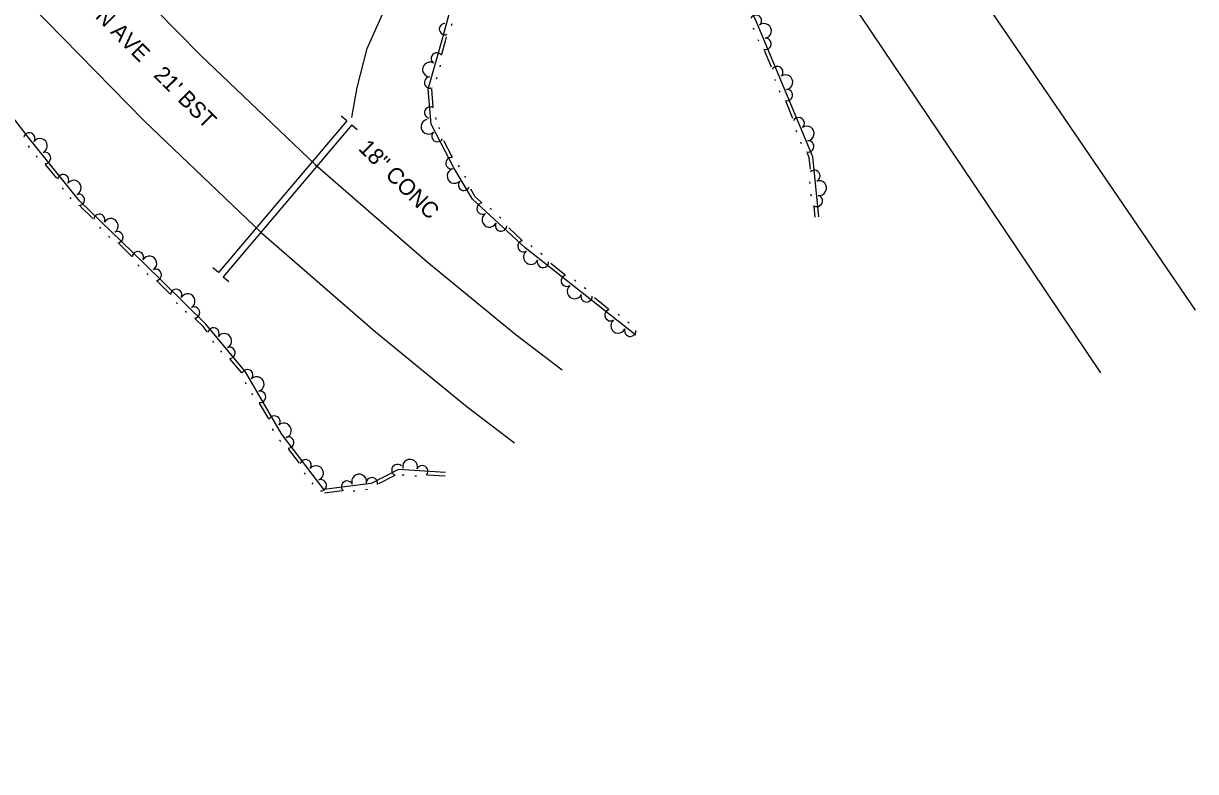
# Model space of a CAD drawing. Extents: x 2030130 to 2036320, y 723205 to 762423.
# Drawn here: x 2034404.8 to 2034673.1, y 759268.4 to 759439.7 of the extents above; entities that cross this region are included whole.
import ezdxf

# ---------------------------------------------------------------- set-up
doc = ezdxf.new("R2010")
doc.units = 0
for name, color, linetype in [('Draft_Station Labels Major', 7, 'Continuous'), ('Draft_Station Tics Major', 7, 'Continuous'), ('Draft_Station Tics Minor', 7, 'Continuous'), ('Old_Level_23', 7, 'Continuous'), ('Old_Level_26', 7, 'Continuous'), ('Prop Alignment Horizontal', 7, 'Continuous')]:
    doc.layers.add(name, color=color, linetype=linetype)

msp = doc.modelspace()

# ---------------------------------------------------------------- linework, layer by layer
at = {"layer": 'Draft_Station Labels Major'}
for points in [[(2034673.1, 759374.03), (2034641.13, 759420.91), (2034612.37, 759462.99), (2034584.85, 759503.64), (2034556.5, 759545.4), (2034528.56, 759586.42), (2034500.61, 759627.72), (2034473.04, 759669.67), (2034444.47, 759710.51), (2034416.72, 759751.28), (2034388.73, 759792.32), (2034360.74, 759833.62)], [(2034339.29, 759819.51), (2034367.32, 759778.28), (2034395.22, 759737.17), (2034423.09, 759695.79), (2034451.3, 759654.89), (2034478.88, 759613.26), (2034507.24, 759572.41), (2034535.18, 759531.29), (2034563.29, 759490.2), (2034591.25, 759449.01), (2034619.59, 759406.87), (2034651.36, 759359.7)], [(2034193.98, 759703.56), (2034287.73, 759602.79), (2034370.61, 759511.86), (2034419.72, 759458.43), (2034445.33, 759432.37), (2034471.55, 759407.33), (2034497.11, 759385.14), (2034517.55, 759368.37), (2034528.08, 759360.37)], [(2034181.13, 759691.91), (2034274.16, 759588.48), (2034357, 759497.6), (2034406.36, 759443.89), (2034432.44, 759417.35), (2034459.25, 759391.75), (2034485.39, 759369.06), (2034506.34, 759351.88), (2034517.18, 759343.65)]]:
    msp.add_lwpolyline(points, dxfattribs=at)
at = {"layer": 'Draft_Station Tics Major'}
for points in [[(2034544.97, 759368.28), (2034519.62, 759388.26), (2034507.55, 759399.45), (2034503.31, 759406.6), (2034498.11, 759416.6), (2034497.43, 759424.62), (2034500.6, 759435.9), (2034503.15, 759445.18), (2034505.1, 759457.43), (2034504.57, 759469.06), (2034502.54, 759482.83), (2034501.29, 759493.73), (2034505.68, 759503.68), (2034511.5, 759511.58), (2034516.43, 759515.13), (2034527.13, 759508.33), (2034541.93, 759494.81), (2034557.48, 759466.95), (2034572.3, 759440.67), (2034585.41, 759409.2), (2034586.75, 759395.36)], [(2034501.4, 759336.81), (2034490.6, 759337.52), (2034484.36, 759334.29), (2034473.58, 759332.95), (2034463.89, 759345.71), (2034455.6, 759359.89), (2034446.5, 759370.82), (2034432.26, 759384.88), (2034417.64, 759399.08), (2034405.88, 759413.63), (2034393.67, 759429.47), (2034382.54, 759442.06), (2034369.68, 759457.9), (2034353.76, 759468), (2034338.78, 759465.82), (2034335.89, 759451.72), (2034333.06, 759435.72), (2034328.81, 759415.39), (2034335.67, 759393.1), (2034347.17, 759361.24), (2034361.18, 759331.95), (2034373.76, 759305.96), (2034386.26, 759281.41), (2034393.72, 759268.38)], [(2034502.79, 759439.22), (2034502.9, 759439.62)], [(2034571.8, 759438.67), (2034571.95, 759438.29)], [(2034500.53, 759432.61), (2034501.39, 759435.68), (2034501.63, 759436.57)], [(2034572.9, 759436.02), (2034573.06, 759435.64)], [(2034574.38, 759433.53), (2034575.96, 759429.74)], [(2034500.15, 759429.74), (2034500.26, 759430.13)], [(2034499.37, 759426.97), (2034499.48, 759427.37)], [(2034576.68, 759426.93), (2034576.84, 759426.56)], [(2034498.6, 759420.52), (2034498.26, 759424.61)], [(2034577.79, 759424.28), (2034577.95, 759423.91)], [(2034579.27, 759421.79), (2034580.85, 759418.01)], [(2034499.26, 759417.7), (2034499.22, 759418.11)], [(2034500.07, 759415.5), (2034499.88, 759415.87)], [(2034581.57, 759415.2), (2034581.73, 759414.82)], [(2034406.19, 759411.28), (2034405.93, 759411.6)], [(2034502.92, 759409.13), (2034501.03, 759412.77)], [(2034582.68, 759412.55), (2034582.83, 759412.17)], [(2034408, 759409.05), (2034407.74, 759409.37)], [(2034584.16, 759410.05), (2034584.6, 759408.99), (2034584.86, 759406.3)], [(2034412.44, 759404.21), (2034409.86, 759407.39)], [(2034504.6, 759406.84), (2034504.39, 759407.2)], [(2034506.06, 759404.37), (2034505.85, 759404.73)], [(2034584.73, 759403.4), (2034584.77, 759402.99)], [(2034413.93, 759401.72), (2034413.67, 759402.04)], [(2034415.74, 759399.48), (2034415.48, 759399.8)], [(2034509.56, 759398.71), (2034508.19, 759399.97), (2034507.17, 759401.69)], [(2034585.01, 759400.55), (2034585.05, 759400.14)], [(2034420.69, 759394.98), (2034417.75, 759397.83)], [(2034511.94, 759397.06), (2034511.64, 759397.33)], [(2034585.69, 759397.73), (2034585.93, 759395.28)], [(2034514.05, 759395.1), (2034513.75, 759395.38)], [(2034422.47, 759392.68), (2034422.17, 759392.97)], [(2034518.88, 759390.06), (2034515.87, 759392.85)], [(2034424.52, 759390.68), (2034424.23, 759390.97)], [(2034429.52, 759386.4), (2034426.58, 759389.26)], [(2034521.25, 759388.54), (2034520.93, 759388.8)], [(2034523.5, 759386.77), (2034523.18, 759387.02)], [(2034431.29, 759384.11), (2034431, 759384.4)], [(2034528.73, 759382.13), (2034525.5, 759384.67)], [(2034433.33, 759382.1), (2034433.04, 759382.39)], [(2034531.23, 759380.67), (2034530.91, 759380.93)], [(2034438.28, 759377.78), (2034435.37, 759380.66)], [(2034533.49, 759378.9), (2034533.17, 759379.15)], [(2034440.04, 759375.47), (2034439.75, 759375.76)], [(2034538.71, 759374.26), (2034535.49, 759376.8)], [(2034442.08, 759373.46), (2034441.79, 759373.74)], [(2034541.22, 759372.81), (2034540.9, 759373.06)], [(2034446.87, 759369.09), (2034445.89, 759370.27), (2034444.12, 759372.02)], [(2034543.47, 759371.03), (2034543.15, 759371.28)], [(2034448.39, 759366.62), (2034448.13, 759366.94)], [(2034450.23, 759364.42), (2034449.97, 759364.73)], [(2034454.74, 759359.63), (2034452.12, 759362.79)], [(2034455.8, 759357.09), (2034455.6, 759357.45)], [(2034457.26, 759354.62), (2034457.05, 759354.97)], [(2034460.92, 759349.16), (2034458.85, 759352.7)], [(2034462.02, 759346.47), (2034461.81, 759346.83)], [(2034463.67, 759343.96), (2034463.43, 759344.28)], [(2034467.97, 759338.98), (2034465.49, 759342.24)], [(2034469.38, 759336.44), (2034469.13, 759336.77)], [(2034489.66, 759336.11), (2034486.02, 759334.22)], [(2034491.91, 759336.2), (2034491.5, 759336.23)], [(2034494.77, 759336.01), (2034494.36, 759336.04)], [(2034501.34, 759335.99), (2034497.25, 759336.26)], [(2034471.12, 759334.16), (2034470.87, 759334.48)], [(2034477.76, 759332.64), (2034473.69, 759332.14)], [(2034480.66, 759332.59), (2034480.25, 759332.54)], [(2034483.51, 759332.94), (2034483.1, 759332.89)]]:
    msp.add_lwpolyline(points, dxfattribs=at)
for centre, radius, start, end in [((2034572.46, 759440.28), 1.3, 311.0445, 151.8411), ((2034501.28, 759438.36), 1.3, 93.0647, 293.8613), ((2034574.32, 759437.94), 1.69, 278.5733, 126.6458), ((2034574.67, 759434.98), 1.3, 253.3781, 94.1746), ((2034499.41, 759431.65), 1.3, 35.0959, 235.8925), ((2034497.84, 759429.11), 1.69, 60.2912, 268.3637), ((2034577.35, 759428.54), 1.3, 311.0445, 151.8411), ((2034497.85, 759426.12), 1.3, 92.7624, 293.559), ((2034579.21, 759426.21), 1.69, 278.5733, 126.6458), ((2034579.56, 759423.24), 1.3, 253.3781, 94.1746), ((2034497.89, 759419.23), 1.3, 55.6136, 256.4101), ((2034497.49, 759416.01), 1.69, 103.4348, 311.5073), ((2034582.24, 759416.81), 1.3, 311.0445, 151.8411), ((2034584.1, 759414.47), 1.69, 278.5733, 126.6458), ((2034406.12, 759413.33), 1.3, 327.4059, 168.2024), ((2034408.56, 759411.62), 1.69, 294.9347, 143.0072), ((2034499.55, 759413.84), 1.3, 135.906, 336.7026), ((2034584.44, 759411.51), 1.3, 253.3781, 94.1746), ((2034409.73, 759408.87), 1.3, 269.7394, 110.536), ((2034502.76, 759407.66), 1.3, 78.2395, 279.0361), ((2034413.85, 759403.77), 1.3, 327.4059, 168.2024), ((2034503.46, 759404.74), 1.69, 106.6121, 314.6846), ((2034585.84, 759404.75), 1.3, 293.9804, 134.777), ((2034416.3, 759402.05), 1.69, 294.9347, 143.0072), ((2034505.63, 759402.69), 1.3, 139.0833, 339.8798), ((2034586.93, 759401.97), 1.69, 261.5092, 109.5817), ((2034417.47, 759399.3), 1.3, 269.7394, 110.536), ((2034586.39, 759399.03), 1.3, 236.3139, 77.1105), ((2034509.9, 759397.27), 1.3, 97.9332, 298.7298), ((2034422.15, 759394.71), 1.3, 334.2699, 175.0665), ((2034424.78, 759393.3), 1.69, 301.7987, 149.8712), ((2034511.45, 759394.72), 1.69, 123.1285, 331.201), ((2034426.27, 759390.71), 1.3, 276.6034, 117.4), ((2034514.11, 759393.37), 1.3, 155.5997, 356.3963), ((2034519.23, 759388.63), 1.3, 97.9332, 298.7298), ((2034430.97, 759386.14), 1.3, 334.2699, 175.0665), ((2034433.6, 759384.71), 1.69, 301.3225, 149.395), ((2034520.95, 759386.17), 1.69, 127.7212, 335.7937), ((2034523.71, 759385.04), 1.3, 160.1924, 0.989), ((2034435.07, 759382.11), 1.3, 276.1272, 116.9238), ((2034529.18, 759380.72), 1.3, 102.526, 303.3225), ((2034439.74, 759377.5), 1.3, 333.7937, 174.5903), ((2034530.93, 759378.3), 1.69, 127.7212, 335.7937), ((2034442.36, 759376.07), 1.69, 301.3225, 149.395), ((2034533.69, 759377.17), 1.3, 160.1924, 0.989), ((2034443.82, 759373.47), 1.3, 276.1272, 116.9238), ((2034539.17, 759372.85), 1.3, 102.526, 303.3225), ((2034540.92, 759370.43), 1.69, 127.7212, 335.7937), ((2034448.29, 759368.67), 1.3, 328.1991, 168.9956), ((2034450.76, 759366.99), 1.69, 295.7279, 143.8004), ((2034543.68, 759369.3), 1.3, 160.1924, 0.989), ((2034451.96, 759364.26), 1.3, 270.5326, 111.3292), ((2034456.04, 759359.13), 1.3, 318.7538, 159.5503), ((2034458.2, 759357.07), 1.69, 286.2826, 134.3551), ((2034458.94, 759354.17), 1.3, 261.0873, 101.8839), ((2034462.25, 759348.51), 1.3, 318.7538, 159.5503), ((2034464.41, 759346.45), 1.69, 286.2826, 134.3551), ((2034465.4, 759343.72), 1.3, 267.9857, 108.7823), ((2034469.37, 759338.5), 1.3, 325.6522, 166.4488), ((2034471.76, 759336.71), 1.69, 293.181, 141.2535), ((2034490.38, 759337.41), 1.3, 45.8557, 246.6523), ((2034493.27, 759338.17), 1.69, 342.1708, 190.2433), ((2034496.08, 759337.16), 1.3, 316.9755, 157.7721), ((2034472.84, 759333.92), 1.3, 267.9857, 108.7823), ((2034481.63, 759334.77), 1.69, 353.0314, 201.1039), ((2034484.55, 759334.38), 1.3, 348.1893, 188.9858), ((2034478.88, 759333.61), 1.3, 25.5026, 226.2991)]:
    msp.add_arc(centre, radius, start, end, dxfattribs=at)
at = {"layer": 'Draft_Station Tics Minor'}
for p, q in [((2034478.79, 759417.39), (2034477.54, 759418.45)), ((2034479.92, 759416.44), (2034481.17, 759415.38)), ((2034449.4, 759382.62), (2034448.15, 759383.68)), ((2034450.53, 759381.67), (2034451.78, 759380.61))]:
    msp.add_line(p, q, dxfattribs=at)
for points in [[(2034478.79, 759417.39), (2034449.4, 759382.62)], [(2034479.92, 759416.44), (2034450.53, 759381.67)]]:
    msp.add_lwpolyline(points, dxfattribs=at)
at = {"layer": 'Prop Alignment Horizontal'}
msp.add_lwpolyline([(2034479.99, 759418.12), (2034481.16, 759424.99), (2034483.43, 759433.89), (2034486.69, 759441.06), (2034492.5, 759453.12), (2034494.65, 759461.77), (2034496.19, 759474.47), (2034499.03, 759483.66), (2034504.67, 759491.37), (2034508.51, 759497.91), (2034511.45, 759503.71), (2034513.89, 759511.14), (2034512.55, 759518.41), (2034509.92, 759522.72), (2034505.76, 759528.02), (2034495.35, 759540.99)], dxfattribs=at)

# ---------------------------------------------------------------- texts
at = {"layer": 'Old_Level_23'}
msp.add_text("ALSTON AVE   21' BST", height=3.6909, rotation=314.856, dxfattribs=at).set_placement((2034409.61, 759452.53))
at = {"layer": 'Old_Level_26'}
msp.add_text('18" CONC', height=3.691, rotation=315.3581, dxfattribs=at).set_placement((2034481.27, 759410.82))

doc.saveas('drawing.dxf')
